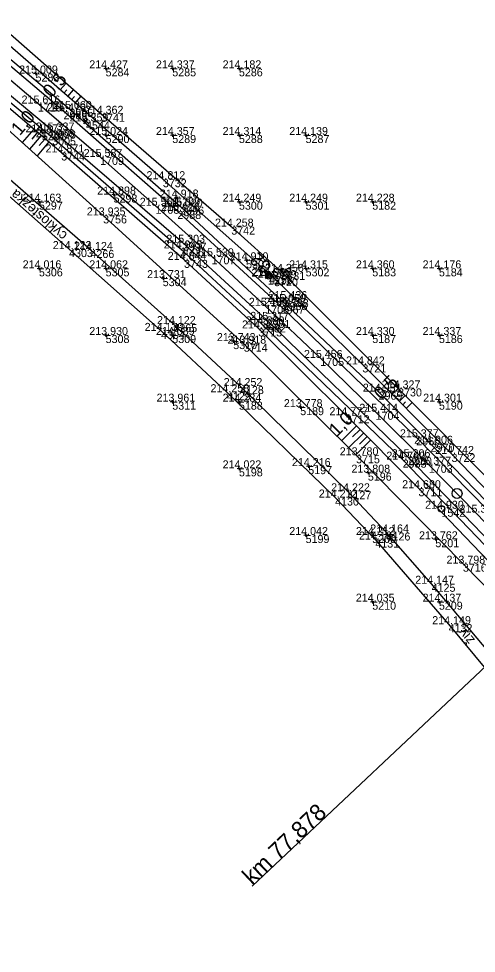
# Model space of a CAD drawing. Extents: x -556590 to -554855, y -1137918 to -1135717.
# Drawn here: x -555963 to -555894.4, y -1136242.7 to -1136102.6 of the extents above; entities that cross this region are included whole.
import ezdxf

# ---------------------------------------------------------------- set-up
doc = ezdxf.new("R2010")
doc.units = 0
for name, color, linetype in [('Vrstva 1', 7, 'Continuous'), ('Vrstva 11', 7, 'Continuous'), ('Vrstva 4', 7, 'Continuous'), ('Vrstva 48', 7, 'Continuous'), ('Vrstva 49', 7, 'Continuous'), ('Vrstva 5', 7, 'Continuous'), ('Vrstva 51', 7, 'Continuous'), ('Vrstva 60', 7, 'Continuous'), ('Vrstva 61', 7, 'Continuous'), ('Vrstva 7', 7, 'Continuous')]:
    doc.layers.add(name, color=color, linetype=linetype)

msp = doc.modelspace()

# ---------------------------------------------------------------- linework, layer by layer
at = {"layer": 'Vrstva 1'}
msp.add_lwpolyline([(-555832.42, -1136244.84), (-555839.96, -1136236.28), (-555847.06, -1136228.24), (-555854.3, -1136220.08), (-555861.27, -1136212.3), (-555867.2, -1136205.74), (-555873.44, -1136198.92), (-555880.49, -1136191.32), (-555887.28, -1136184.11), (-555894.45, -1136176.65), (-555901.51, -1136169.46), (-555909.49, -1136161.51), (-555917.8, -1136153.44), (-555926.06, -1136145.62), (-555934.11, -1136138.19), (-555942.52, -1136130.61), (-555950.83, -1136123.29), (-555960.15, -1136115.28), (-555966.69, -1136109.79)], dxfattribs=at)
at = {"layer": 'Vrstva 11'}
for p, q in [((-555925.87, -1136140.79), (-555925.13, -1136141.47)), ((-555925.11, -1136140.81), (-555925.82, -1136140.84)), ((-555925, -1136141.18), (-555925.43, -1136141.2))]:
    msp.add_line(p, q, dxfattribs=at)
msp.add_circle((-555925.5, -1136141.13), 0.503, dxfattribs=at)
msp.add_arc((-555925.5, -1136141.13), 0.503, 317.3007, 137.3007, dxfattribs=at)
at = {"layer": 'Vrstva 4'}
for points in [[(-555923.74, -1136145.62), (-555939.24, -1136131.4), (-555956.32, -1136116.44), (-555971.9, -1136103.23), (-555992.92, -1136086.51), (-555997.91, -1136082.27)], [(-555997.91, -1136082.27), (-555992.59, -1136085.78), (-555972.17, -1136102.03), (-555955.43, -1136116.09), (-555938.79, -1136130.74), (-555923.29, -1136145.05)], [(-555925.85, -1136147.73), (-555938.44, -1136136.16), (-555958.03, -1136119.33), (-555976.1, -1136104.24), (-555996.32, -1136088.06), (-556000.41, -1136085.03)], [(-556000.41, -1136085.03), (-555999.71, -1136086.49), (-555996.42, -1136089.2), (-555976.32, -1136105.14), (-555958.02, -1136120.33), (-555938.82, -1136137.01), (-555926.53, -1136148.41)], [(-555923.29, -1136145.05), (-555909.05, -1136158.5), (-555901.25, -1136166.31), (-555887.79, -1136180.16), (-555881.94, -1136186.03), (-555875.34, -1136193.25), (-555855.8, -1136214.83), (-555838.02, -1136234.81), (-555828.68, -1136245.44)], [(-555829.18, -1136246.07), (-555838.74, -1136235.05), (-555856.1, -1136215.62), (-555876.91, -1136192.69), (-555887.27, -1136181.76), (-555903.4, -1136165.34), (-555923.74, -1136145.62)], [(-555831.3, -1136248.38), (-555841.29, -1136237.03), (-555858.39, -1136217.74), (-555876.45, -1136197.84), (-555890.69, -1136182.7), (-555904.62, -1136168.33), (-555925.85, -1136147.73)], [(-555926.53, -1136148.41), (-555905.43, -1136168.7), (-555890.59, -1136184.1), (-555875.69, -1136200.05), (-555858.38, -1136219.09), (-555841.01, -1136238.72), (-555832.06, -1136249.03)]]:
    msp.add_lwpolyline(points, dxfattribs=at)
at = {"layer": 'Vrstva 48'}
for p, q in [((-555956.82, -1136113.24), (-555955.93, -1136112.21)), ((-555956.26, -1136113.73), (-555955.82, -1136113.22)), ((-555955.69, -1136114.22), (-555954.81, -1136113.2)), ((-555955.13, -1136114.71), (-555954.69, -1136114.21)), ((-555954.56, -1136115.21), (-555953.68, -1136114.19)), ((-555960.79, -1136119.1), (-555962.52, -1136121.13)), ((-555959.65, -1136120.07), (-555961.4, -1136122.13)), ((-555960.22, -1136119.58), (-555961.09, -1136120.61)), ((-555958.51, -1136121.04), (-555960.29, -1136123.14)), ((-555959.08, -1136120.56), (-555959.96, -1136121.59)), ((-555907.02, -1136158.89), (-555906.13, -1136158)), ((-555906.49, -1136159.42), (-555906.05, -1136158.98)), ((-555905.96, -1136159.95), (-555905.07, -1136159.06)), ((-555905.43, -1136160.48), (-555904.99, -1136160.04)), ((-555904.9, -1136161.01), (-555904.01, -1136160.13)), ((-555912.36, -1136163.64), (-555914.6, -1136165.88)), ((-555911.3, -1136164.71), (-555913.54, -1136166.94)), ((-555911.83, -1136164.18), (-555912.95, -1136165.29)), ((-555910.24, -1136165.77), (-555912.47, -1136167.99)), ((-555910.77, -1136165.24), (-555911.89, -1136166.35))]:
    msp.add_line(p, q, dxfattribs=at)
at = {"layer": 'Vrstva 49'}
for p, q in [((-555949.75, -1136109.95), (-555950.25, -1136110.05)), ((-555950.05, -1136109.75), (-555949.95, -1136110.25)), ((-555939.75, -1136109.95), (-555940.25, -1136110.05)), ((-555940.05, -1136109.75), (-555939.95, -1136110.25)), ((-555929.75, -1136109.95), (-555930.25, -1136110.05)), ((-555930.05, -1136109.75), (-555929.95, -1136110.25)), ((-555960.27, -1136110.74), (-555960.76, -1136110.83)), ((-555960.56, -1136110.54), (-555960.47, -1136111.03)), ((-555959.32, -1136119.55), (-555959.81, -1136119.64)), ((-555959.61, -1136119.35), (-555959.52, -1136119.84)), ((-555949.75, -1136119.95), (-555950.25, -1136120.05)), ((-555950.05, -1136119.75), (-555949.95, -1136120.25)), ((-555939.75, -1136119.95), (-555940.25, -1136120.05)), ((-555940.05, -1136119.75), (-555939.95, -1136120.25)), ((-555929.75, -1136119.95), (-555930.25, -1136120.05)), ((-555930.05, -1136119.75), (-555929.95, -1136120.25)), ((-555919.75, -1136119.95), (-555920.25, -1136120.05)), ((-555920.05, -1136119.75), (-555919.95, -1136120.25)), ((-555959.75, -1136129.95), (-555960.25, -1136130.05)), ((-555960.05, -1136129.75), (-555959.95, -1136130.25)), ((-555948.56, -1136128.88), (-555949.05, -1136128.97)), ((-555948.85, -1136128.68), (-555948.76, -1136129.17)), ((-555939.16, -1136129.33), (-555939.65, -1136129.42)), ((-555939.45, -1136129.13), (-555939.36, -1136129.62)), ((-555929.75, -1136129.95), (-555930.25, -1136130.05)), ((-555930.05, -1136129.75), (-555929.95, -1136130.25)), ((-555919.75, -1136129.95), (-555920.25, -1136130.05)), ((-555920.05, -1136129.75), (-555919.95, -1136130.25)), ((-555909.75, -1136129.95), (-555910.25, -1136130.05)), ((-555910.05, -1136129.75), (-555909.95, -1136130.25)), ((-555960.05, -1136139.75), (-555959.95, -1136140.25)), ((-555950.05, -1136139.75), (-555949.95, -1136140.25)), ((-555928.68, -1136138.74), (-555929.17, -1136138.83)), ((-555928.98, -1136138.54), (-555928.88, -1136139.03)), ((-555920.05, -1136139.75), (-555919.95, -1136140.25)), ((-555910.05, -1136139.75), (-555909.95, -1136140.25)), ((-555900.05, -1136139.75), (-555899.95, -1136140.25)), ((-555959.75, -1136139.95), (-555960.25, -1136140.05)), ((-555949.75, -1136139.95), (-555950.25, -1136140.05)), ((-555941.47, -1136141.23), (-555941.38, -1136141.72)), ((-555919.75, -1136139.95), (-555920.25, -1136140.05)), ((-555909.75, -1136139.95), (-555910.25, -1136140.05)), ((-555899.75, -1136139.95), (-555900.25, -1136140.05)), ((-555941.18, -1136141.43), (-555941.67, -1136141.52)), ((-555949.75, -1136149.95), (-555950.25, -1136150.05)), ((-555950.05, -1136149.75), (-555949.95, -1136150.25)), ((-555939.75, -1136149.95), (-555940.25, -1136150.05)), ((-555940.05, -1136149.75), (-555939.95, -1136150.25)), ((-555930.61, -1136150.86), (-555931.1, -1136150.96)), ((-555930.9, -1136150.66), (-555930.81, -1136151.15)), ((-555909.75, -1136149.95), (-555910.25, -1136150.05)), ((-555910.05, -1136149.75), (-555909.95, -1136150.25)), ((-555899.75, -1136149.95), (-555900.25, -1136150.05)), ((-555900.05, -1136149.75), (-555899.95, -1136150.25)), ((-555939.75, -1136159.95), (-555940.25, -1136160.05)), ((-555940.05, -1136159.75), (-555939.95, -1136160.25)), ((-555929.75, -1136159.95), (-555930.25, -1136160.05)), ((-555930.05, -1136159.75), (-555929.95, -1136160.25)), ((-555920.57, -1136160.77), (-555921.06, -1136160.87)), ((-555920.86, -1136160.57), (-555920.76, -1136161.06)), ((-555899.75, -1136159.95), (-555900.25, -1136160.05)), ((-555900.05, -1136159.75), (-555899.95, -1136160.25)), ((-555929.75, -1136169.95), (-555930.25, -1136170.05)), ((-555930.05, -1136169.75), (-555929.95, -1136170.25)), ((-555919.35, -1136169.62), (-555919.84, -1136169.71)), ((-555919.64, -1136169.42), (-555919.55, -1136169.91)), ((-555910.42, -1136170.6), (-555910.91, -1136170.69)), ((-555910.71, -1136170.4), (-555910.62, -1136170.89)), ((-555919.75, -1136179.95), (-555920.25, -1136180.05)), ((-555920.05, -1136179.75), (-555919.95, -1136180.25)), ((-555909.75, -1136179.95), (-555910.25, -1136180.05)), ((-555910.05, -1136179.75), (-555909.95, -1136180.25)), ((-555900.57, -1136180.39), (-555900.48, -1136180.88)), ((-555900.28, -1136180.59), (-555900.77, -1136180.68)), ((-555909.75, -1136189.95), (-555910.25, -1136190.05)), ((-555910.05, -1136189.75), (-555909.95, -1136190.25)), ((-555899.75, -1136189.95), (-555900.25, -1136190.05)), ((-555900.05, -1136189.75), (-555899.95, -1136190.25))]:
    msp.add_line(p, q, dxfattribs=at)
for points in [[(-555924.72, -1136141.47), (-555941.41, -1136126.63), (-555967.87, -1136103.64), (-555972.49, -1136100.32), (-555990.89, -1136085.05), (-555996.53, -1136080.04)], [(-555996.53, -1136080.04), (-555992.96, -1136081.46), (-555990.31, -1136083.36), (-555974.84, -1136096.31), (-555967.21, -1136102.32), (-555950.68, -1136116.82), (-555931.15, -1136133.74), (-555923.63, -1136140.53)], [(-555927.09, -1136149.01), (-555938.23, -1136138.73), (-555956.66, -1136122.62), (-555972.75, -1136108.93), (-555987, -1136097.42), (-555999.04, -1136088.45), (-556000.59, -1136088.06), (-556001.3, -1136088.49), (-556001.98, -1136090.42), (-556001.65, -1136092.92)], [(-556001.65, -1136092.92), (-556000.62, -1136091.37), (-555999.97, -1136091.06), (-555987.12, -1136100.39), (-555969.31, -1136115.02), (-555950.37, -1136132.06), (-555929.27, -1136151.3)], [(-555857.61, -1136209.27), (-555864.16, -1136201.99), (-555875.56, -1136189.23), (-555891.42, -1136172.76), (-555906.12, -1136158.01), (-555923.63, -1136140.53)], [(-555924.72, -1136141.47), (-555911.48, -1136154.41), (-555898.1, -1136167.84), (-555884.88, -1136181.51), (-555876.43, -1136190.27), (-555864.62, -1136203.3), (-555857.61, -1136209.27)], [(-555833.11, -1136250.23), (-555845.42, -1136235.8), (-555865.29, -1136213.2), (-555884.38, -1136192.48), (-555903.06, -1136172.98), (-555913.97, -1136162.03), (-555927.09, -1136149.01)], [(-555929.27, -1136151.3), (-555912.43, -1136168.04), (-555896.4, -1136184.29), (-555880.18, -1136200.83), (-555865.51, -1136217.21), (-555848.26, -1136236.84), (-555834.96, -1136252.17)]]:
    msp.add_lwpolyline(points, dxfattribs=at)
at = {"layer": 'Vrstva 5'}
msp.add_line((-555884.54, -1136191.68), (-555928, -1136232.69), dxfattribs=at)
at = {"layer": 'Vrstva 51'}
for points in [[(-555931.8, -1136158.58), (-555941.68, -1136149.38), (-555955.48, -1136137.11), (-555971.89, -1136122.69), (-555982.31, -1136114.16), (-555990.71, -1136107.94), (-555993.07, -1136106.38), (-555995.34, -1136105.22), (-555999.48, -1136103.83), (-556003.11, -1136102.76)], [(-555929.84, -1136157.66), (-555939.84, -1136148.36), (-555952.27, -1136137.24), (-555973.32, -1136118.91)], [(-555844.03, -1136257.56), (-555848.54, -1136252.78), (-555852.79, -1136247.62), (-555864.18, -1136233.05), (-555877.97, -1136215.51), (-555889.52, -1136201.13), (-555901.09, -1136187.31), (-555907.85, -1136179.62), (-555913.71, -1136173.44), (-555929.84, -1136157.66)], [(-555931.8, -1136158.58), (-555915.57, -1136174.38), (-555909.54, -1136180.68), (-555898.54, -1136193.37), (-555887.09, -1136207.18), (-555873.58, -1136224.29), (-555860.8, -1136240.56), (-555852.9, -1136250.63), (-555848.76, -1136255.49), (-555845.44, -1136259.04)]]:
    msp.add_lwpolyline(points, dxfattribs=at)
at = {"layer": 'Vrstva 60'}
for p, q in [((-555950, -1136110), (-555950, -1136110)), ((-555940, -1136110), (-555940, -1136110)), ((-555930, -1136110), (-555930, -1136110)), ((-555960.52, -1136110.78), (-555960.52, -1136110.78)), ((-555960.15, -1136115.28), (-555960.15, -1136115.28)), ((-555956.32, -1136116.44), (-555956.32, -1136116.44)), ((-555955.43, -1136116.09), (-555955.43, -1136116.09)), ((-555950.68, -1136116.82), (-555950.68, -1136116.82)), ((-555952.94, -1136117.96), (-555952.94, -1136117.96)), ((-555959.57, -1136119.6), (-555959.57, -1136119.6)), ((-555958.03, -1136119.33), (-555958.03, -1136119.33)), ((-555950, -1136120), (-555950, -1136120)), ((-555940, -1136120), (-555940, -1136120)), ((-555930, -1136120), (-555930, -1136120)), ((-555920, -1136120), (-555920, -1136120)), ((-555958.02, -1136120.33), (-555958.02, -1136120.33)), ((-555956.66, -1136122.62), (-555956.66, -1136122.62)), ((-555950.83, -1136123.29), (-555950.83, -1136123.29)), ((-555941.41, -1136126.63), (-555941.41, -1136126.63)), ((-555960, -1136130), (-555960, -1136130)), ((-555948.81, -1136128.93), (-555948.81, -1136128.93)), ((-555939.4, -1136129.38), (-555939.4, -1136129.38)), ((-555930, -1136130), (-555930, -1136130)), ((-555920, -1136130), (-555920, -1136130)), ((-555910, -1136130), (-555910, -1136130)), ((-555942.52, -1136130.61), (-555942.52, -1136130.61)), ((-555939.24, -1136131.4), (-555939.24, -1136131.4)), ((-555938.79, -1136130.74), (-555938.79, -1136130.74)), ((-555950.37, -1136132.06), (-555950.37, -1136132.06)), ((-555931.15, -1136133.74), (-555931.15, -1136133.74)), ((-555938.82, -1136137.01), (-555938.82, -1136137.01)), ((-555938.44, -1136136.16), (-555938.44, -1136136.16)), ((-555955.48, -1136137.11), (-555955.48, -1136137.11)), ((-555952.27, -1136137.24), (-555952.27, -1136137.24)), ((-555934.11, -1136138.19), (-555934.11, -1136138.19)), ((-555938.23, -1136138.73), (-555938.23, -1136138.73)), ((-555928.93, -1136138.79), (-555928.93, -1136138.79)), ((-555960, -1136140), (-555960, -1136140)), ((-555950, -1136140), (-555950, -1136140)), ((-555925.67, -1136141.23), (-555925.67, -1136141.23)), ((-555925.5, -1136141.13), (-555925.5, -1136141.13)), ((-555923.63, -1136140.53), (-555923.63, -1136140.53)), ((-555920, -1136140), (-555920, -1136140)), ((-555910, -1136140), (-555910, -1136140)), ((-555900, -1136140), (-555900, -1136140)), ((-555941.43, -1136141.47), (-555941.43, -1136141.47)), ((-555924.72, -1136141.47), (-555924.72, -1136141.47)), ((-555923.29, -1136145.05), (-555923.29, -1136145.05)), ((-555923.11, -1136144.62), (-555923.11, -1136144.62)), ((-555926.06, -1136145.62), (-555926.06, -1136145.62)), ((-555923.74, -1136145.62), (-555923.74, -1136145.62)), ((-555925.85, -1136147.73), (-555925.85, -1136147.73)), ((-555941.68, -1136149.38), (-555941.68, -1136149.38)), ((-555939.84, -1136148.36), (-555939.84, -1136148.36)), ((-555927.09, -1136149.01), (-555927.09, -1136149.01)), ((-555926.53, -1136148.41), (-555926.53, -1136148.41)), ((-555950, -1136150), (-555950, -1136150)), ((-555940, -1136150), (-555940, -1136150)), ((-555930.86, -1136150.91), (-555930.86, -1136150.91)), ((-555910, -1136150), (-555910, -1136150)), ((-555900, -1136150), (-555900, -1136150)), ((-555929.27, -1136151.3), (-555929.27, -1136151.3)), ((-555917.8, -1136153.44), (-555917.8, -1136153.44)), ((-555911.48, -1136154.41), (-555911.48, -1136154.41)), ((-555929.84, -1136157.66), (-555929.84, -1136157.66)), ((-555906.12, -1136158.01), (-555906.12, -1136158.01)), ((-555931.8, -1136158.58), (-555931.8, -1136158.58)), ((-555909.05, -1136158.5), (-555909.05, -1136158.5)), ((-555940, -1136160), (-555940, -1136160)), ((-555930, -1136160), (-555930, -1136160)), ((-555920.81, -1136160.82), (-555920.81, -1136160.82)), ((-555900, -1136160), (-555900, -1136160)), ((-555913.97, -1136162.03), (-555913.97, -1136162.03)), ((-555909.49, -1136161.51), (-555909.49, -1136161.51)), ((-555903.4, -1136165.34), (-555903.4, -1136165.34)), ((-555901.25, -1136166.31), (-555901.25, -1136166.31)), ((-555898.1, -1136167.84), (-555898.1, -1136167.84)), ((-555912.43, -1136168.04), (-555912.43, -1136168.04)), ((-555905.43, -1136168.7), (-555905.43, -1136168.7)), ((-555904.62, -1136168.33), (-555904.62, -1136168.33)), ((-555930, -1136170), (-555930, -1136170)), ((-555919.6, -1136169.67), (-555919.6, -1136169.67)), ((-555910.66, -1136170.64), (-555910.66, -1136170.64)), ((-555901.51, -1136169.46), (-555901.51, -1136169.46)), ((-555913.71, -1136173.44), (-555913.71, -1136173.44)), ((-555903.06, -1136172.98), (-555903.06, -1136172.98)), ((-555915.57, -1136174.38), (-555915.57, -1136174.38)), ((-555899.62, -1136176.06), (-555899.62, -1136176.06)), ((-555894.45, -1136176.65), (-555894.45, -1136176.65)), ((-555920, -1136180), (-555920, -1136180)), ((-555910, -1136180), (-555910, -1136180)), ((-555907.85, -1136179.62), (-555907.85, -1136179.62)), ((-555909.54, -1136180.68), (-555909.54, -1136180.68)), ((-555900.53, -1136180.64), (-555900.53, -1136180.64)), ((-555896.4, -1136184.29), (-555896.4, -1136184.29)), ((-555901.09, -1136187.31), (-555901.09, -1136187.31)), ((-555910, -1136190), (-555910, -1136190)), ((-555900, -1136190), (-555900, -1136190)), ((-555898.54, -1136193.37), (-555898.54, -1136193.37))]:
    msp.add_line(p, q, dxfattribs=at)
at = {"layer": 'Vrstva 7'}
for p, q in [((-555952.56, -1136118.28), (-555953.32, -1136117.63)), ((-555953.27, -1136118.34), (-555952.62, -1136117.58)), ((-555926.04, -1136140.89), (-555925.3, -1136141.56)), ((-555925.33, -1136140.86), (-555926.01, -1136141.59)), ((-555922.75, -1136144.97), (-555923.47, -1136144.28)), ((-555923.45, -1136144.99), (-555922.77, -1136144.26)), ((-555899.57, -1136176.06), (-555899.67, -1136176.06))]:
    msp.add_line(p, q, dxfattribs=at)
for centre, radius in [((-555897.28, -1136173.76), 0.75), ((-555899.62, -1136176.06), 0.5)]:
    msp.add_circle(centre, radius, dxfattribs=at)

# ---------------------------------------------------------------- texts
at = {"layer": 'Vrstva 11'}
msp.add_text('32', height=2, rotation=137.3007, dxfattribs=at).set_placement((-555925.02, -1136139.48))
at = {"layer": 'Vrstva 48'}
for s, rotation, p in [('0,5', 49.0152, (-555958.13, -1136114.52)), ('1,0', 49.6326, (-555962.86, -1136120.19)), ('0,5', 44.8932, (-555908.6, -1136159.86)), ('1,0', 44.903, (-555915.32, -1136165.35))]:
    msp.add_text(s, height=2, rotation=rotation, dxfattribs=at).set_placement(p)
at = {"layer": 'Vrstva 5'}
msp.add_text('km 77,878', height=2.5, rotation=43.2859, dxfattribs=at).set_placement((-555928.04, -1136232.58))
at = {"layer": 'Vrstva 51'}
for s, rotation, p in [('cyklostezka', 138.9371, (-555955.64, -1136134.87)), ('živ.', 129.6694, (-555894.54, -1136195.7))]:
    msp.add_text(s, height=1.5, rotation=rotation, dxfattribs=at).set_placement(p)
at = {"layer": 'Vrstva 60'}
for s, p in [('5284', (-555950, -1136111.2)), ('5285', (-555940, -1136111.2)), ('5286', (-555930, -1136111.2)), ('5283', (-555960.52, -1136111.98)), ('1710', (-555960.15, -1136116.48)), ('2989', (-555956.32, -1136117.64)), ('2995', (-555955.43, -1136117.29)), ('3741', (-555950.68, -1136118.02)), ('4544', (-555952.94, -1136119.16)), ('5291', (-555959.57, -1136120.8)), ('2998', (-555958.03, -1136120.53)), ('5290', (-555950, -1136121.2)), ('5289', (-555940, -1136121.2)), ('5288', (-555930, -1136121.2)), ('5287', (-555920, -1136121.2)), ('3005', (-555958.02, -1136121.53)), ('3744', (-555956.66, -1136123.82)), ('1709', (-555950.83, -1136124.49)), ('3732', (-555941.41, -1136127.83)), ('5297', (-555960, -1136131.2)), ('5298', (-555948.81, -1136130.13)), ('5299', (-555939.4, -1136130.58)), ('5300', (-555930, -1136131.2)), ('5301', (-555920, -1136131.2)), ('5182', (-555910, -1136131.2)), ('1708', (-555942.52, -1136131.81)), ('2988', (-555939.24, -1136132.6)), ('2996', (-555938.79, -1136131.94)), ('3756', (-555950.37, -1136133.26)), ('3742', (-555931.15, -1136134.94)), ('3006', (-555938.82, -1136138.21)), ('2997', (-555938.44, -1136137.35)), ('4303', (-555955.48, -1136138.31)), ('4266', (-555952.27, -1136138.44)), ('1707', (-555934.11, -1136139.39)), ('3743', (-555938.23, -1136139.93)), ('5303', (-555928.93, -1136139.99)), ('5306', (-555960, -1136141.2)), ('5305', (-555950, -1136141.2)), ('1511', (-555925.67, -1136142.43)), ('4258', (-555925.5, -1136142.33)), ('3731', (-555923.63, -1136141.73)), ('5302', (-555920, -1136141.2)), ('5183', (-555910, -1136141.2)), ('5184', (-555900, -1136141.2)), ('5304', (-555941.43, -1136142.67)), ('3720', (-555924.72, -1136142.67)), ('2968', (-555923.29, -1136146.26)), ('4538', (-555923.11, -1136145.82)), ('1706', (-555926.06, -1136146.82)), ('2967', (-555923.74, -1136146.82)), ('2981', (-555925.85, -1136148.93)), ('4304', (-555941.68, -1136150.58)), ('4265', (-555939.84, -1136149.56)), ('3713', (-555927.09, -1136150.21)), ('2982', (-555926.53, -1136149.61)), ('5308', (-555950, -1136151.2)), ('5309', (-555940, -1136151.2)), ('5310', (-555930.86, -1136152.11)), ('5187', (-555910, -1136151.2)), ('5186', (-555900, -1136151.2)), ('3714', (-555929.27, -1136152.5)), ('1705', (-555917.8, -1136154.64)), ('3721', (-555911.48, -1136155.61)), ('4128', (-555929.84, -1136158.86)), ('3730', (-555906.12, -1136159.21)), ('4129', (-555931.8, -1136159.78)), ('2969', (-555909.05, -1136159.7)), ('5311', (-555940, -1136161.2)), ('5188', (-555930, -1136161.2)), ('5189', (-555920.81, -1136162.02)), ('5190', (-555900, -1136161.2)), ('3712', (-555913.97, -1136163.23)), ('1704', (-555909.49, -1136162.71)), ('2966', (-555903.4, -1136166.54)), ('2970', (-555901.25, -1136167.51)), ('3722', (-555898.1, -1136169.04)), ('3715', (-555912.43, -1136169.24)), ('2983', (-555905.43, -1136169.9)), ('2980', (-555904.62, -1136169.53)), ('5198', (-555930, -1136171.2)), ('5197', (-555919.6, -1136170.87)), ('5196', (-555910.66, -1136171.84)), ('1703', (-555901.51, -1136170.66)), ('4127', (-555913.71, -1136174.64)), ('3711', (-555903.06, -1136174.18)), ('4130', (-555915.57, -1136175.58)), ('1542', (-555899.62, -1136177.26)), ('5199', (-555920, -1136181.2)), ('5200', (-555910, -1136181.2)), ('4126', (-555907.85, -1136180.82)), ('4131', (-555909.54, -1136181.88)), ('5201', (-555900.53, -1136181.83)), ('3716', (-555896.4, -1136185.5)), ('4125', (-555901.09, -1136188.51)), ('5210', (-555910, -1136191.2)), ('5209', (-555900, -1136191.2)), ('4132', (-555898.54, -1136194.57))]:
    msp.add_text(s, height=1.2, dxfattribs=at).set_placement(p)
at = {"layer": 'Vrstva 61'}
for s, p in [('214.427', (-555952.45, -1136110)), ('214.337', (-555942.45, -1136110)), ('214.182', (-555932.45, -1136110)), ('215.009', (-555962.97, -1136110.78)), ('215.616', (-555962.61, -1136115.28)), ('215.476', (-555958.77, -1136116.44)), ('215.060', (-555957.88, -1136116.09)), ('214.362', (-555953.13, -1136116.82)), ('215.359', (-555955.39, -1136117.96)), ('214.877', (-555962.02, -1136119.6)), ('215.337', (-555960.48, -1136119.33)), ('215.024', (-555952.45, -1136120)), ('214.357', (-555942.45, -1136120)), ('214.314', (-555932.45, -1136120)), ('214.139', (-555922.45, -1136120)), ('214.968', (-555960.47, -1136120.33)), ('214.871', (-555959.01, -1136122.62)), ('215.587', (-555953.29, -1136123.29)), ('214.812', (-555943.86, -1136126.63)), ('214.898', (-555951.26, -1136128.93)), ('214.918', (-555941.86, -1136129.38)), ('214.163', (-555962.45, -1136130)), ('215.561', (-555944.88, -1136130.61)), ('215.020', (-555941.24, -1136130.74)), ('214.249', (-555932.45, -1136130)), ('214.249', (-555922.45, -1136130)), ('214.228', (-555912.45, -1136130)), ('213.935', (-555952.82, -1136132.06)), ('215.426', (-555941.69, -1136131.4)), ('214.258', (-555933.6, -1136133.74)), ('215.303', (-555940.89, -1136136.16)), ('214.122', (-555957.93, -1136137.11)), ('214.124', (-555954.72, -1136137.24)), ('214.945', (-555941.28, -1136137.01)), ('215.530', (-555936.57, -1136138.19)), ('214.844', (-555940.68, -1136138.73)), ('214.910', (-555931.38, -1136138.79)), ('214.016', (-555962.45, -1136140)), ('214.062', (-555952.45, -1136140)), ('214.356', (-555926.08, -1136140.53)), ('214.315', (-555922.46, -1136140)), ('214.360', (-555912.45, -1136140)), ('214.176', (-555902.45, -1136140)), ('213.731', (-555943.78, -1136141.47)), ('215.675', (-555928.13, -1136141.23)), ('214.980', (-555927.95, -1136141.13)), ('214.919', (-555927.17, -1136141.47)), ('215.059', (-555925.74, -1136145.05)), ('215.436', (-555925.56, -1136144.62)), ('215.496', (-555928.51, -1136145.62)), ('215.476', (-555926.19, -1136145.62)), ('215.317', (-555928.3, -1136147.73)), ('214.139', (-555944.14, -1136149.38)), ('214.122', (-555942.29, -1136148.36)), ('214.822', (-555929.54, -1136149.01)), ('214.890', (-555928.98, -1136148.41)), ('213.930', (-555952.45, -1136150)), ('214.089', (-555942.45, -1136150)), ('214.330', (-555912.45, -1136150)), ('214.337', (-555902.45, -1136150)), ('213.743', (-555933.31, -1136150.91)), ('213.918', (-555931.72, -1136151.3)), ('215.456', (-555920.25, -1136153.44)), ('214.842', (-555913.93, -1136154.41)), ('214.252', (-555932.29, -1136157.66)), ('214.258', (-555934.26, -1136158.58)), ('214.931', (-555911.41, -1136158.5)), ('214.327', (-555908.58, -1136158.01)), ('213.961', (-555942.36, -1136160)), ('214.284', (-555932.45, -1136160)), ('214.301', (-555902.36, -1136160)), ('213.778', (-555923.26, -1136160.82)), ('214.777', (-555916.42, -1136162.03)), ('215.414', (-555911.94, -1136161.51)), ('215.377', (-555905.85, -1136165.34)), ('214.906', (-555903.7, -1136166.31)), ('213.780', (-555914.88, -1136168.04)), ('214.760', (-555907.88, -1136168.7)), ('215.206', (-555907.08, -1136168.33)), ('214.742', (-555900.55, -1136167.84)), ('214.022', (-555932.45, -1136170)), ('214.216', (-555922.05, -1136169.67)), ('215.377', (-555903.96, -1136169.46)), ('213.808', (-555913.12, -1136170.64)), ('214.680', (-555905.51, -1136172.98)), ('214.212', (-555918.02, -1136174.38)), ('214.222', (-555916.16, -1136173.44)), ('214.930', (-555902.07, -1136176.06)), ('215.340', (-555896.9, -1136176.65)), ('214.042', (-555922.45, -1136180)), ('214.212', (-555912.45, -1136180)), ('214.164', (-555910.3, -1136179.62)), ('214.184', (-555911.99, -1136180.68)), ('213.762', (-555902.98, -1136180.64)), ('213.798', (-555898.86, -1136184.29)), ('214.147', (-555903.55, -1136187.31)), ('214.035', (-555912.46, -1136190)), ('214.137', (-555902.45, -1136190)), ('214.149', (-555901, -1136193.37))]:
    msp.add_text(s, height=1.2, dxfattribs=at).set_placement(p)

doc.saveas('drawing.dxf')
